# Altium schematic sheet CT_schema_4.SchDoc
size 493 x 398 mm
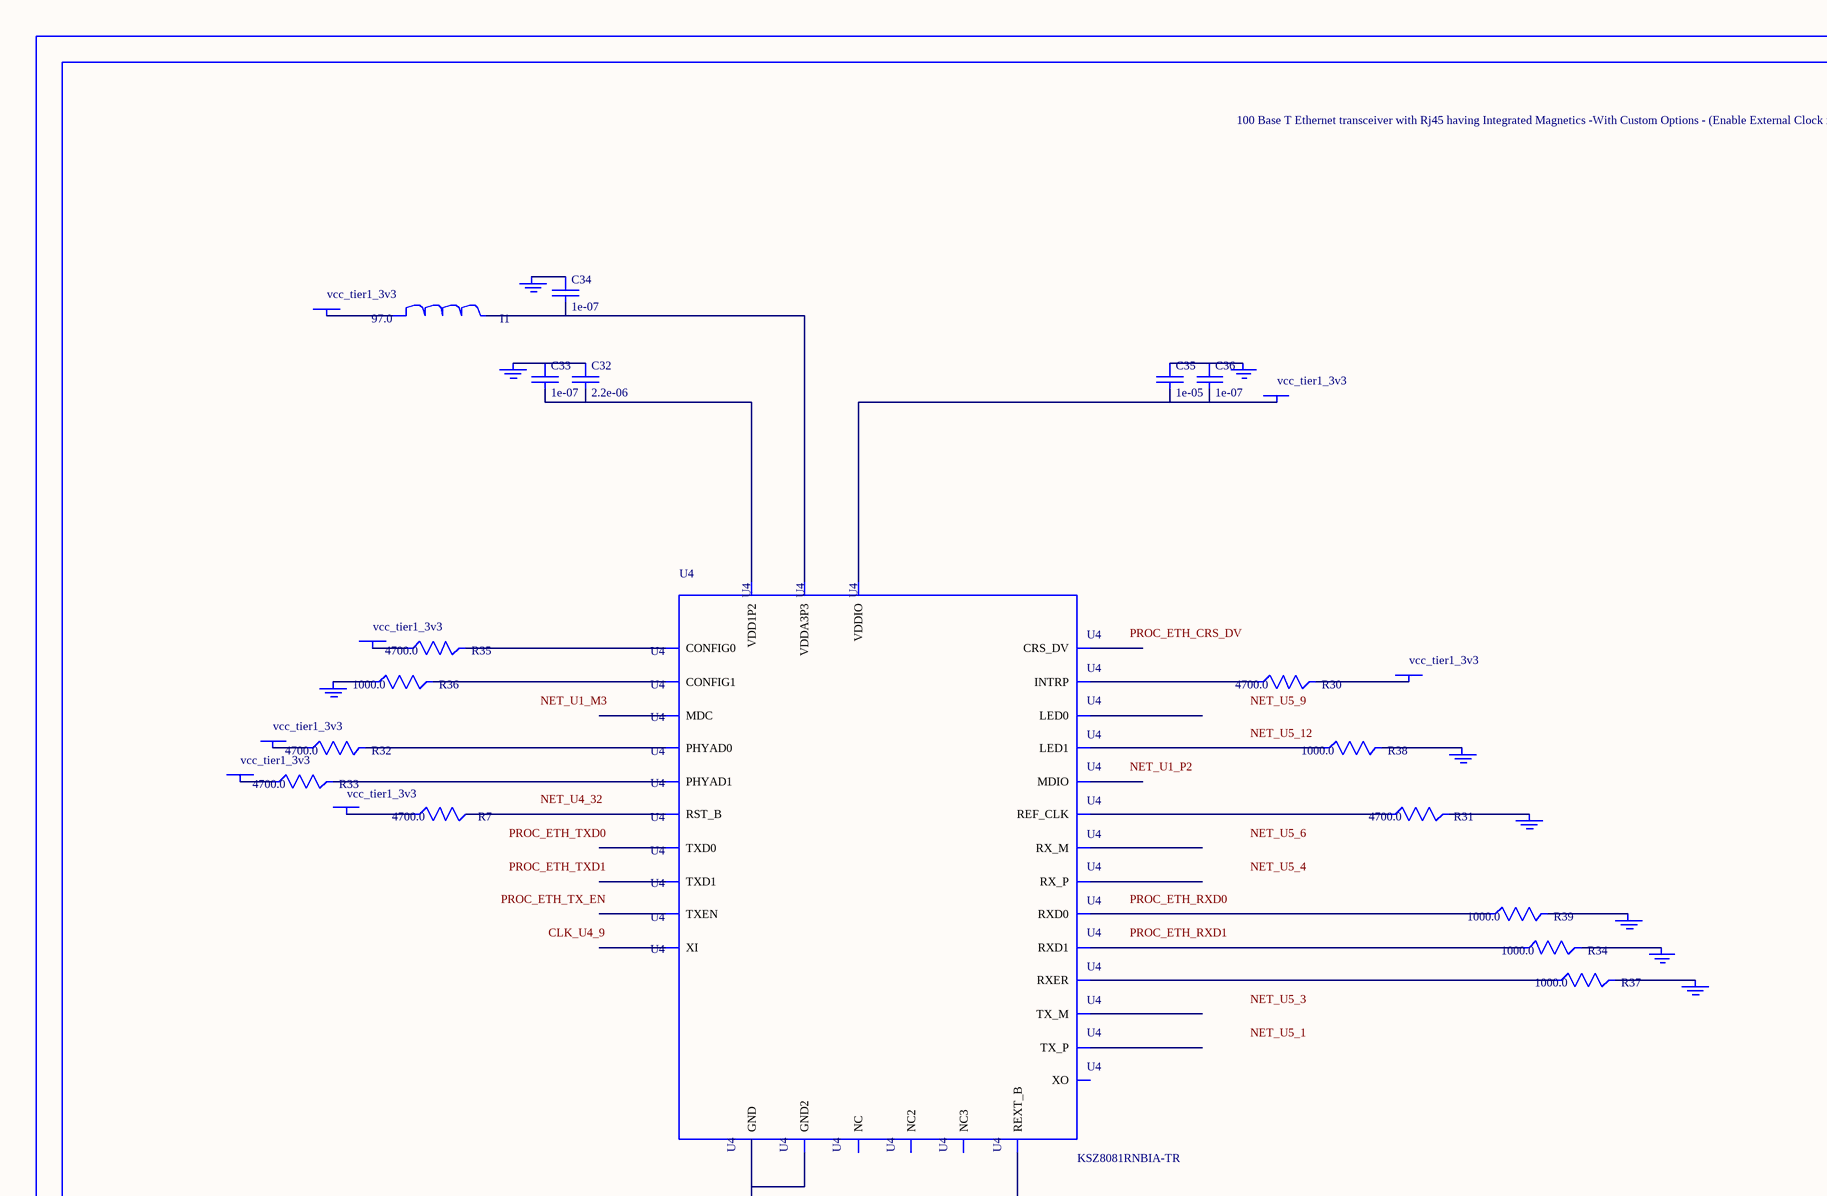
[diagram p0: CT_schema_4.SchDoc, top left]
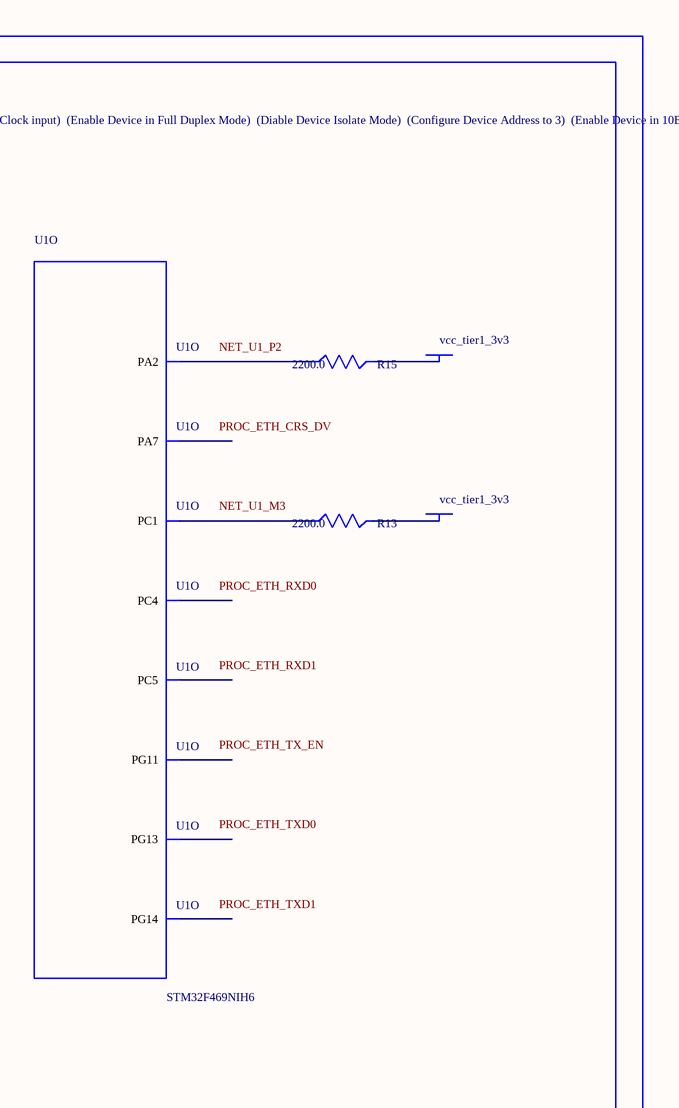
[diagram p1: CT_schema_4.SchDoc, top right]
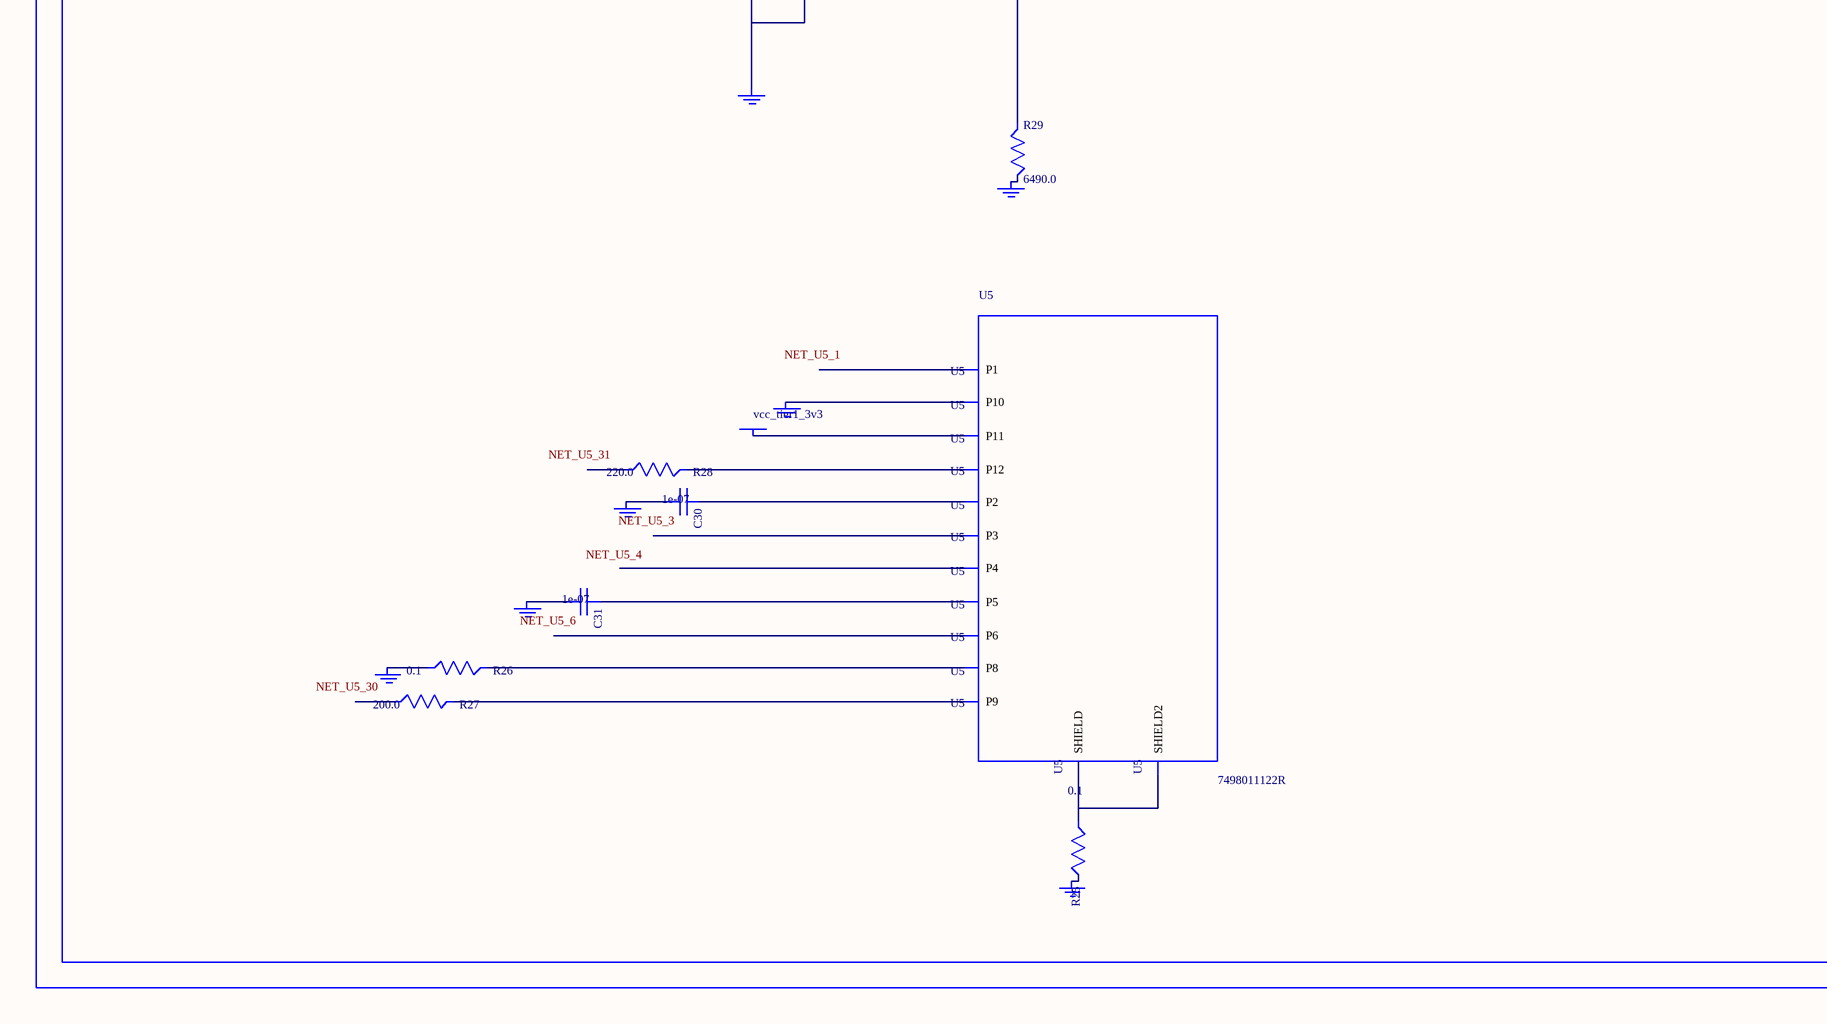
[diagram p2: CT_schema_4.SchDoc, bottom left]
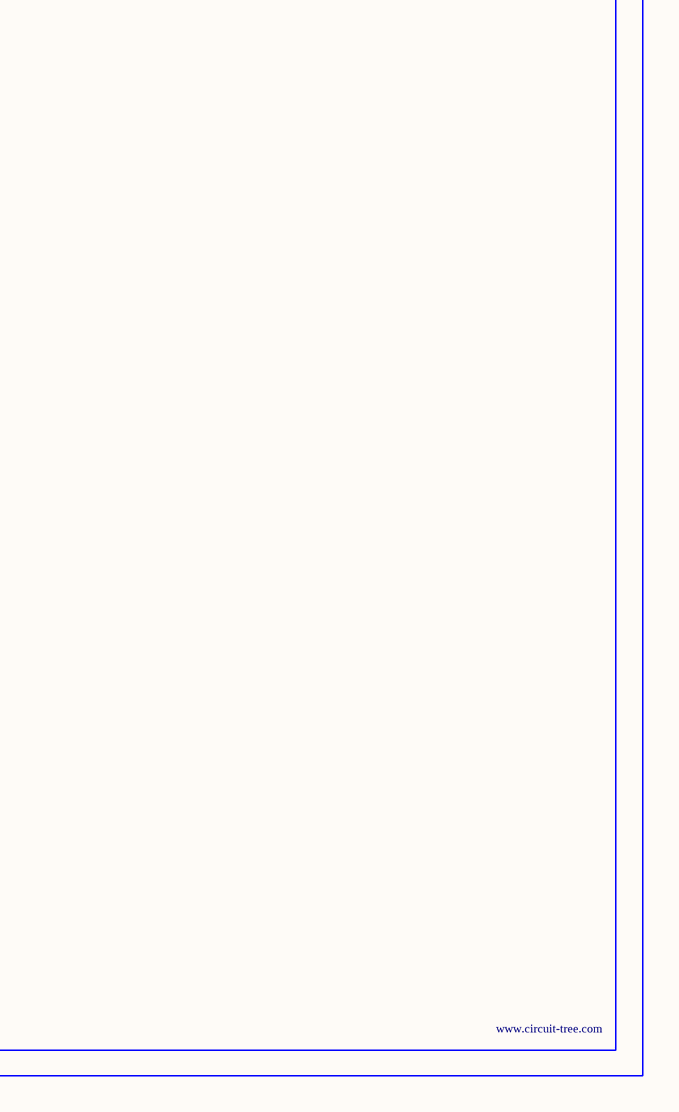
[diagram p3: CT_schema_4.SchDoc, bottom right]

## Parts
BORDER3  (no value)
C30  1e-07  [C0402]
C31  1e-07  [C0402]
C32  2.2e-06  [C0603]
C33  1e-07  [C0402]
C34  1e-07  [C0402]
C35  1e-05  [C0805]
C36  1e-07  [C0402]
GND_INSTANCE_3_0  (no value)
GND_INSTANCE_3_1  (no value)
GND_INSTANCE_3_2  (no value)
GND_INSTANCE_3_3  (no value)
GND_INSTANCE_3_4  (no value)
GND_INSTANCE_3_5  (no value)
GND_INSTANCE_3_6  (no value)
GND_INSTANCE_3_7  (no value)
GND_INSTANCE_3_8  (no value)
GND_INSTANCE_3_9  (no value)
GND_INSTANCE_3_10  (no value)
GND_INSTANCE_3_11  (no value)
GND_INSTANCE_3_12  (no value)
GND_INSTANCE_3_13  (no value)
GND_INSTANCE_3_14  (no value)
GND_INSTANCE_3_15  (no value)
I1  97.0  [R0603]
POWER_INSTANCE_3_0  vcc_tier1_3v3
POWER_INSTANCE_3_1  vcc_tier1_3v3
POWER_INSTANCE_3_2  vcc_tier1_3v3
POWER_INSTANCE_3_3  vcc_tier1_3v3
POWER_INSTANCE_3_4  vcc_tier1_3v3
POWER_INSTANCE_3_5  vcc_tier1_3v3
POWER_INSTANCE_3_6  vcc_tier1_3v3
POWER_INSTANCE_3_7  vcc_tier1_3v3
POWER_INSTANCE_3_8  vcc_tier1_3v3
POWER_INSTANCE_3_9  vcc_tier1_3v3
R7  4700.0  [R0603]
R13  2200.0  [R0603]
R15  2200.0  [R0603]
R25  0.1  [R0603]
R26  0.1  [R0603]
R27  200.0  [R0603]
R28  220.0  [R0603]
R29  6490.0  [R0603]
R30  4700.0  [R0603]
R31  4700.0  [R0603]
R32  4700.0  [R0603]
R33  4700.0  [R0603]
R34  1000.0  [R0603]
R35  4700.0  [R0603]
R36  1000.0  [R0603]
R37  1000.0  [R0603]
R38  1000.0  [R0603]
R39  1000.0  [R0603]
U1  STM32F469NIH6  [TFBGA216]  (part O of 17)
U4  KSZ8081RNBIA-TR  [QFN-32]
U5  7498011122R  [7498011122R]

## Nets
NetC30_1: C30.1 U5.2(P2)
NetC30_2: C30.2 GND_INSTANCE_3_11.0(GND)
NetC31_1: C31.1 U5.5(P5)
NetC31_2: C31.2 GND_INSTANCE_3_12.0(GND)
NetC32_1: C32.1 C33.1 GND_INSTANCE_3_0.0(GND)
NetC32_2: C32.2 C33.2 U4.2(VDD1P2)
NetC34_1: C34.1 GND_INSTANCE_3_1.0(GND)
NetC34_2: C34.2 I1.2 U4.3(VDDA3P3)
NetC35_1: C35.1 C36.1 GND_INSTANCE_3_5.0(GND)
NetC35_2: C35.2 C36.2 POWER_INSTANCE_3_3.0(PWR) U4.17(VDDIO)
NetGND_INSTANCE_3_2_0: GND_INSTANCE_3_2.0(GND) R29.2
NetGND_INSTANCE_3_3_0: GND_INSTANCE_3_3.0(GND) R34.2
NetGND_INSTANCE_3_4_0: GND_INSTANCE_3_4.0(GND) R39.2
NetGND_INSTANCE_3_6_0: GND_INSTANCE_3_6.0(GND) R31.2
NetGND_INSTANCE_3_7_0: GND_INSTANCE_3_7.0(GND) R37.2
NetGND_INSTANCE_3_8_0: GND_INSTANCE_3_8.0(GND) R36.1
NetGND_INSTANCE_3_9_0: GND_INSTANCE_3_9.0(GND) R38.2
NetGND_INSTANCE_3_10_0: GND_INSTANCE_3_10.0(GND) U4.1(GND) U4.EXP(GND2)
NetGND_INSTANCE_3_13_0: GND_INSTANCE_3_13.0(GND) R26.1
NetGND_INSTANCE_3_14_0: GND_INSTANCE_3_14.0(GND) U5.10(P10)
NetGND_INSTANCE_3_15_0: GND_INSTANCE_3_15.0(GND) R25.2
NetI1_1: I1.1 POWER_INSTANCE_3_0.0(PWR)
NetPOWER_INSTANCE_3_1_0: POWER_INSTANCE_3_1.0(PWR) R32.1
NetPOWER_INSTANCE_3_2_0: POWER_INSTANCE_3_2.0(PWR) R33.1
NetPOWER_INSTANCE_3_4_0: POWER_INSTANCE_3_4.0(PWR) R30.2
NetPOWER_INSTANCE_3_5_0: POWER_INSTANCE_3_5.0(PWR) R35.1
NetPOWER_INSTANCE_3_6_0: POWER_INSTANCE_3_6.0(PWR) R7.1
NetPOWER_INSTANCE_3_7_0: POWER_INSTANCE_3_7.0(PWR) R15.2
NetPOWER_INSTANCE_3_8_0: POWER_INSTANCE_3_8.0(PWR) R13.2
NetPOWER_INSTANCE_3_9_0: POWER_INSTANCE_3_9.0(PWR) U5.11(P11)
NetR7_2: R7.2 U4.32(RST_B)
NetR13_1: R13.1 U1.M3(PC1)
NetR15_1: R15.1 U1.P2(PA2)
NetR25_1: R25.1 U5.13(SHIELD) U5.14(SHIELD2)
NetR26_2: R26.2 U5.8(P8)
NetR27_2: R27.2 U5.9(P9)
NetR28_2: R28.2 U5.12(P12)
NetR29_1: R29.1 U4.10(REXT_B)
NetR30_1: R30.1 U4.21(INTRP)
NetR31_1: R31.1 U4.19(REF_CLK)
NetR32_2: R32.2 U4.13(PHYAD0)
NetR33_2: R33.2 U4.14(PHYAD1)
NetR34_1: R34.1 U4.15(RXD1)
NetR35_2: R35.2 U4.28(CONFIG0)
NetR36_2: R36.2 U4.29(CONFIG1)
NetR37_1: R37.1 U4.20(RXER)
NetR38_1: R38.1 U4.31(LED1)
NetR39_1: R39.1 U4.16(RXD0)

Not connected (* = marked no-connect by the designer): R27 1; R28 1; U1 A4(PG14) B3(PG13) B8(PG11) N5(PC4) P5(PC5) R3(PA7); U4 4(RX_M) 5(RX_P) 6(TX_M) 7(TX_P) 8(XO) 9(XI) 11(MDIO) 12(MDC) 18(CRS_DV) 22(NC) 23(TXEN) 24(TXD0) 25(TXD1) 26(NC2) 27(NC3) 30(LED0); U5 1(P1) 3(P3) 4(P4) 6(P6)

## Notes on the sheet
- Labels drawn without touching a wire or pin: CLK_U4_9, NET_U1_M3, NET_U1_P2, NET_U4_32, NET_U5_1, NET_U5_3, NET_U5_4, NET_U5_6, NET_U5_9, NET_U5_12, NET_U5_30, NET_U5_31, PROC_ETH_CRS_DV, PROC_ETH_RXD0, PROC_ETH_RXD1, PROC_ETH_TX_EN, PROC_ETH_TXD0, PROC_ETH_TXD1

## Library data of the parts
BORDER3 = BORDER_PAGE3
C30 C31 C33 C34 C36 = C0402C104K3RACTU
C32 = C0603C225K8RACTU
C35 = C0805C106K8RACTU
GND_INSTANCE_3_0-GND_INSTANCE_3_15 = GND
I1 = I1
POWER_INSTANCE_3_0-POWER_INSTANCE_3_9 = PWR
R7 R30-R33 R35 = RC0603JR-074K7L
R13 R15 = RC0603JR-072K2L
R25 R26 = ERJ-3RSFR10V
R27 = RC0603JR-07200RL
R28 = RC0603JR-07220RL
R29 = ERJ-3EKF6491V
R34 R36-R39 = RC0603JR-071KL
